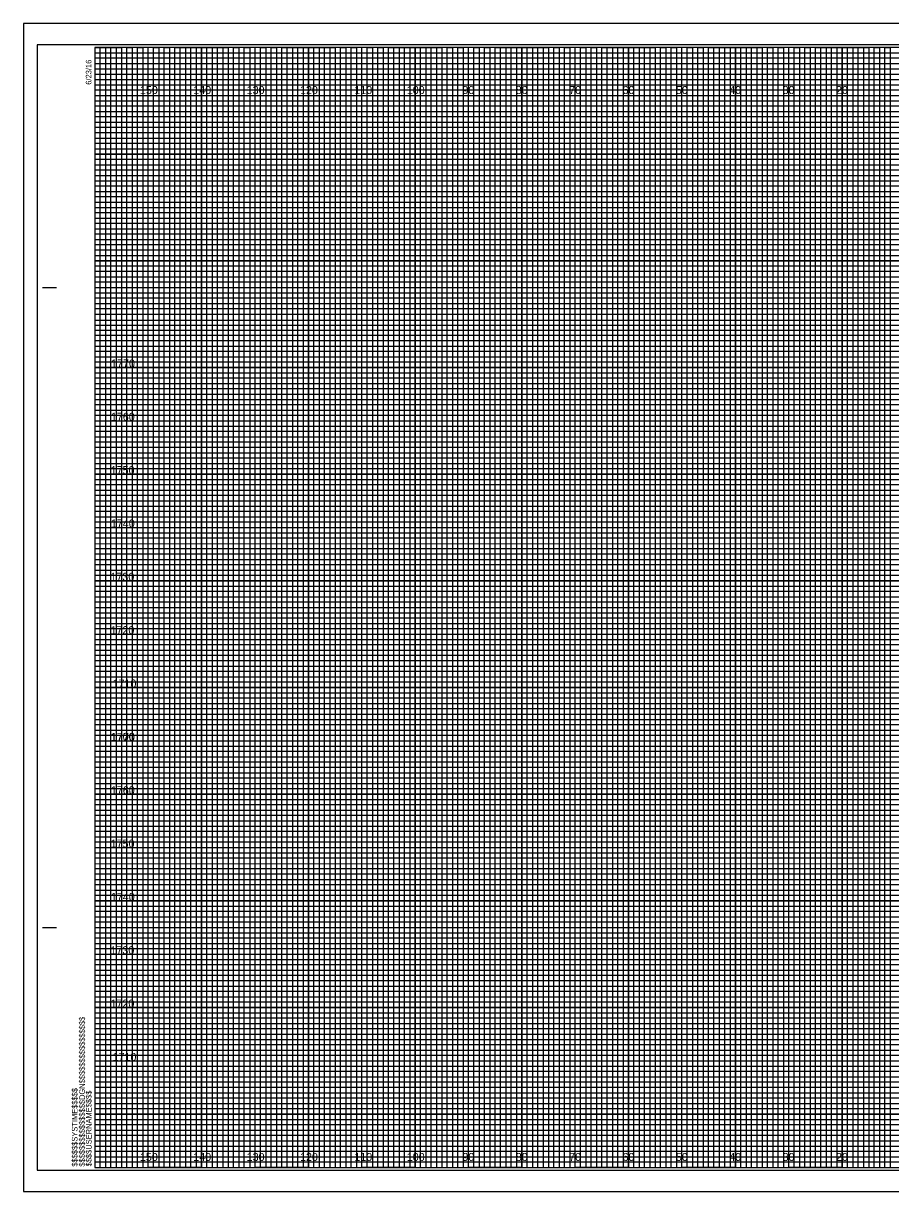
# Model space of a CAD drawing. Extents: x -15 to 323, y -5 to 6170.
# Drawn here: x -13.4 to 149.1, y 5275.5 to 5494.5 of the extents above; entities that cross this region are included whole.
import ezdxf

# ---------------------------------------------------------------- set-up
doc = ezdxf.new("R2010")
doc.units = 0
for name, color, linetype in [('Prop XS DDE', 7, 'Continuous'), ('Prop XS DDE Slope Text', 7, 'Continuous'), ('Prop XS DDE Text', 7, 'Continuous'), ('Prop XS Earthwork Shape', 7, 'Continuous'), ('Prop XS Noise Wall', 7, 'Continuous'), ('Prop XS Retaining Wall', 7, 'Continuous'), ('Prop XS Station Labels', 7, 'Continuous'), ('Scratch_Level_3', 7, 'Continuous'), ('Scratch_Level_7', 7, 'Continuous'), ('Scratch_Level_8', 7, 'Continuous'), ('Sheet Cross Section Grid Minor 1 CELL', 7, 'Continuous')]:
    doc.layers.add(name, color=color, linetype=linetype)

msp = doc.modelspace()

# ---------------------------------------------------------------- linework, layer by layer
at = {"layer": 'Prop XS DDE'}
msp.add_lwpolyline([(-13.4, 5275.5), (323.3, 5275.5), (323.3, 5494.5), (-13.4, 5494.5)], close=True, dxfattribs=at)
at = {"layer": 'Prop XS DDE Slope Text'}
msp.add_lwpolyline([(-10.8, 5279.5), (322.4, 5279.5), (322.4, 5490.5), (-10.8, 5490.5)], close=True, dxfattribs=at)
at = {"layer": 'Prop XS DDE Text'}
for p, q in [((10, 5280), (10, 5490)), ((20, 5280), (20, 5490)), ((30, 5280), (30, 5490)), ((40, 5280), (40, 5490)), ((50, 5280), (50, 5490)), ((60, 5280), (60, 5490)), ((70, 5280), (70, 5490)), ((80, 5280), (80, 5490)), ((90, 5280), (90, 5490)), ((100, 5280), (100, 5490)), ((110, 5280), (110, 5490)), ((120, 5280), (120, 5490)), ((130, 5280), (130, 5490)), ((140, 5280), (140, 5490)), ((0, 5480), (320, 5480)), ((0, 5470), (320, 5470)), ((0, 5460), (320, 5460)), ((0, 5450), (320, 5450)), ((0, 5440), (320, 5440)), ((0, 5430), (320, 5430)), ((0, 5420), (320, 5420)), ((0, 5410), (320, 5410)), ((0, 5400), (320, 5400)), ((0, 5390), (320, 5390)), ((0, 5380), (320, 5380)), ((0, 5370), (320, 5370)), ((0, 5360), (320, 5360)), ((0, 5350), (320, 5350)), ((0, 5340), (320, 5340)), ((0, 5330), (320, 5330)), ((0, 5320), (320, 5320)), ((0, 5310), (320, 5310)), ((0, 5300), (320, 5300)), ((0, 5290), (320, 5290))]:
    msp.add_line(p, q, dxfattribs=at)
at = {"layer": 'Prop XS Earthwork Shape'}
for p, q in [((10, 5490), (0, 5490)), ((10, 5280), (10, 5490)), ((30, 5490), (20, 5490)), ((20, 5490), (20, 5280)), ((30, 5280), (30, 5490)), ((50, 5490), (40, 5490)), ((40, 5490), (40, 5280)), ((50, 5280), (50, 5490)), ((70, 5490), (60, 5490)), ((60, 5490), (60, 5280)), ((70, 5280), (70, 5490)), ((90, 5490), (80, 5490)), ((80, 5490), (80, 5280)), ((90, 5280), (90, 5490)), ((110, 5490), (100, 5490)), ((100, 5490), (100, 5280)), ((110, 5280), (110, 5490)), ((130, 5490), (120, 5490)), ((120, 5490), (120, 5280)), ((130, 5280), (130, 5490)), ((150, 5490), (140, 5490)), ((140, 5490), (140, 5280)), ((20, 5280), (10, 5280)), ((40, 5280), (30, 5280)), ((60, 5280), (50, 5280)), ((80, 5280), (70, 5280)), ((100, 5280), (90, 5280)), ((120, 5280), (110, 5280)), ((140, 5280), (130, 5280))]:
    msp.add_line(p, q, dxfattribs=at)
for points in [[(0, 5480), (320, 5480), (320, 5470), (0, 5470)], [(0, 5460), (320, 5460), (320, 5450), (0, 5450)], [(0, 5440), (320, 5440), (320, 5430), (0, 5430)], [(0, 5420), (320, 5420), (320, 5410), (0, 5410)], [(0, 5400), (320, 5400), (320, 5390), (0, 5390)], [(0, 5380), (320, 5380), (320, 5370), (0, 5370)], [(0, 5360), (320, 5360), (320, 5350), (0, 5350)], [(0, 5340), (320, 5340), (320, 5330), (0, 5330)], [(0, 5320), (320, 5320), (320, 5310), (0, 5310)], [(0, 5300), (320, 5300), (320, 5290), (0, 5290)]]:
    msp.add_lwpolyline(points, dxfattribs=at)
at = {"layer": 'Prop XS Noise Wall'}
for p, q in [((-9.8, 5445), (-7.3, 5445)), ((-9.7, 5445), (-7.2, 5445)), ((-9.8, 5325), (-7.3, 5325)), ((-9.7, 5325), (-7.2, 5325)), ((0, 5280), (0, 5280)), ((0, 5280), (0, 5280)), ((0, 5280), (0, 5280)), ((0, 5280), (0, 5280)), ((0, 5280), (0, 5280)), ((0, 5280), (0, 5280)), ((0, 5280), (0, 5280))]:
    msp.add_line(p, q, dxfattribs=at)
msp.add_lwpolyline([(320, 5490), (0, 5490), (0, 5280), (320, 5280)], close=True, dxfattribs=at)
at = {"layer": 'Prop XS Retaining Wall'}
for points in [[(0, 5280), (1, 5280), (1, 5490), (2, 5490), (2, 5280)], [(2, 5280), (3, 5280), (3, 5490), (4, 5490), (4, 5280)], [(5, 5280), (6, 5280), (6, 5490), (7, 5490), (7, 5280)], [(7, 5280), (8, 5280), (8, 5490), (9, 5490), (9, 5280)], [(10, 5280), (11, 5280), (11, 5490), (12, 5490), (12, 5280)], [(12, 5280), (13, 5280), (13, 5490), (14, 5490), (14, 5280)], [(15, 5280), (16, 5280), (16, 5490), (17, 5490), (17, 5280)], [(17, 5280), (18, 5280), (18, 5490), (19, 5490), (19, 5280)], [(20, 5280), (21, 5280), (21, 5490), (22, 5490), (22, 5280)], [(22, 5280), (23, 5280), (23, 5490), (24, 5490), (24, 5280)], [(25, 5280), (26, 5280), (26, 5490), (27, 5490), (27, 5280)], [(27, 5280), (28, 5280), (28, 5490), (29, 5490), (29, 5280)], [(30, 5280), (31, 5280), (31, 5490), (32, 5490), (32, 5280)], [(32, 5280), (33, 5280), (33, 5490), (34, 5490), (34, 5280)], [(35, 5280), (36, 5280), (36, 5490), (37, 5490), (37, 5280)], [(37, 5280), (38, 5280), (38, 5490), (39, 5490), (39, 5280)], [(40, 5280), (41, 5280), (41, 5490), (42, 5490), (42, 5280)], [(42, 5280), (43, 5280), (43, 5490), (44, 5490), (44, 5280)], [(45, 5280), (46, 5280), (46, 5490), (47, 5490), (47, 5280)], [(47, 5280), (48, 5280), (48, 5490), (49, 5490), (49, 5280)], [(50, 5280), (51, 5280), (51, 5490), (52, 5490), (52, 5280)], [(52, 5280), (53, 5280), (53, 5490), (54, 5490), (54, 5280)], [(55, 5280), (56, 5280), (56, 5490), (57, 5490), (57, 5280)], [(57, 5280), (58, 5280), (58, 5490), (59, 5490), (59, 5280)], [(60, 5280), (61, 5280), (61, 5490), (62, 5490), (62, 5280)], [(62, 5280), (63, 5280), (63, 5490), (64, 5490), (64, 5280)], [(65, 5280), (66, 5280), (66, 5490), (67, 5490), (67, 5280)], [(67, 5280), (68, 5280), (68, 5490), (69, 5490), (69, 5280)], [(70, 5280), (71, 5280), (71, 5490), (72, 5490), (72, 5280)], [(72, 5280), (73, 5280), (73, 5490), (74, 5490), (74, 5280)], [(75, 5280), (76, 5280), (76, 5490), (77, 5490), (77, 5280)], [(77, 5280), (78, 5280), (78, 5490), (79, 5490), (79, 5280)], [(80, 5280), (81, 5280), (81, 5490), (82, 5490), (82, 5280)], [(82, 5280), (83, 5280), (83, 5490), (84, 5490), (84, 5280)], [(85, 5280), (86, 5280), (86, 5490), (87, 5490), (87, 5280)], [(87, 5280), (88, 5280), (88, 5490), (89, 5490), (89, 5280)], [(90, 5280), (91, 5280), (91, 5490), (92, 5490), (92, 5280)], [(92, 5280), (93, 5280), (93, 5490), (94, 5490), (94, 5280)], [(95, 5280), (96, 5280), (96, 5490), (97, 5490), (97, 5280)], [(97, 5280), (98, 5280), (98, 5490), (99, 5490), (99, 5280)], [(100, 5280), (101, 5280), (101, 5490), (102, 5490), (102, 5280)], [(102, 5280), (103, 5280), (103, 5490), (104, 5490), (104, 5280)], [(105, 5280), (106, 5280), (106, 5490), (107, 5490), (107, 5280)], [(107, 5280), (108, 5280), (108, 5490), (109, 5490), (109, 5280)], [(110, 5280), (111, 5280), (111, 5490), (112, 5490), (112, 5280)], [(112, 5280), (113, 5280), (113, 5490), (114, 5490), (114, 5280)], [(115, 5280), (116, 5280), (116, 5490), (117, 5490), (117, 5280)], [(117, 5280), (118, 5280), (118, 5490), (119, 5490), (119, 5280)], [(120, 5280), (121, 5280), (121, 5490), (122, 5490), (122, 5280)], [(122, 5280), (123, 5280), (123, 5490), (124, 5490), (124, 5280)], [(125, 5280), (126, 5280), (126, 5490), (127, 5490), (127, 5280)], [(127, 5280), (128, 5280), (128, 5490), (129, 5490), (129, 5280)], [(130, 5280), (131, 5280), (131, 5490), (132, 5490), (132, 5280)], [(132, 5280), (133, 5280), (133, 5490), (134, 5490), (134, 5280)], [(135, 5280), (136, 5280), (136, 5490), (137, 5490), (137, 5280)], [(137, 5280), (138, 5280), (138, 5490), (139, 5490), (139, 5280)], [(140, 5280), (141, 5280), (141, 5490), (142, 5490), (142, 5280)], [(142, 5280), (143, 5280), (143, 5490), (144, 5490), (144, 5280)], [(145, 5280), (146, 5280), (146, 5490), (147, 5490), (147, 5280)], [(147, 5280), (148, 5280), (148, 5490), (149, 5490), (149, 5280)]]:
    msp.add_lwpolyline(points, dxfattribs=at)
at = {"layer": 'Prop XS Station Labels'}
for points in [[(0, 5490), (5, 5490), (5, 5280), (15, 5280), (15, 5490), (25, 5490), (25, 5280), (35, 5280), (35, 5490), (45, 5490), (45, 5280), (55, 5280), (55, 5490), (65, 5490), (65, 5280), (75, 5280), (75, 5490), (85, 5490), (85, 5280), (95, 5280), (95, 5490), (105, 5490), (105, 5280), (115, 5280), (115, 5490), (125, 5490), (125, 5280), (135, 5280), (135, 5490), (145, 5490), (145, 5280), (155, 5280)], [(0, 5485), (275, 5485)], [(0, 5465), (320, 5465), (320, 5475), (0, 5475)], [(0, 5445), (320, 5445), (320, 5455), (0, 5455)], [(0, 5425), (320, 5425), (320, 5435), (0, 5435)], [(0, 5405), (320, 5405), (320, 5415), (0, 5415)], [(0, 5385), (320, 5385), (320, 5395), (0, 5395)], [(0, 5365), (320, 5365), (320, 5375), (0, 5375)], [(0, 5345), (320, 5345), (320, 5355), (0, 5355)], [(0, 5325), (320, 5325), (320, 5335), (0, 5335)], [(0, 5305), (320, 5305), (320, 5315), (0, 5315)], [(0, 5285), (320, 5285), (320, 5295), (0, 5295)]]:
    msp.add_lwpolyline(points, dxfattribs=at)
at = {"layer": 'Scratch_Level_7'}
for p, q in [((323.3, 5494.5), (-13.4, 5494.5)), ((-13.4, 5494.5), (-13.4, 5275.5)), ((-13.4, 5275.5), (323.3, 5275.5))]:
    msp.add_line(p, q, dxfattribs=at)
at = {"layer": 'Sheet Cross Section Grid Minor 1 CELL'}
for p, q in [((0, 5489), (260, 5489)), ((260, 5487.98), (0, 5487.98)), ((0, 5487.98), (0, 5487)), ((0, 5487), (260, 5487)), ((260, 5485.89), (0, 5485.89)), ((0, 5485.89), (0, 5484)), ((0, 5484), (320, 5484))]:
    msp.add_line(p, q, dxfattribs=at)
for points in [[(0, 5483), (270, 5483), (320, 5483), (320, 5482), (0, 5482)], [(0, 5481), (320, 5481), (320, 5479), (0, 5479)], [(0, 5478), (320, 5478), (320, 5477), (0, 5476.98)], [(0, 5476), (320, 5476), (320, 5474), (0, 5474)], [(0, 5473), (320, 5473), (320, 5472), (0, 5472)], [(0, 5471), (320, 5471), (320, 5469), (0, 5469)], [(0, 5468), (320, 5468), (320, 5467), (0, 5467)], [(0, 5466), (320, 5466), (320, 5464), (0, 5464)], [(0, 5463), (320, 5463), (320, 5462), (0, 5462)], [(0, 5461), (320, 5461), (320, 5459), (0, 5459)], [(0, 5458), (320, 5458), (320, 5457), (0, 5457)], [(0, 5456), (320, 5456), (320, 5453.95), (320, 5453), (320, 5452), (0, 5452)], [(0, 5454), (320, 5454), (320, 5453), (0, 5453)], [(0, 5451), (320, 5451), (320, 5449), (0, 5449.03)], [(0, 5449.03), (320, 5449), (320, 5448), (0, 5448)], [(0, 5447), (320, 5447), (320, 5446), (0, 5446)], [(0, 5444), (320, 5444), (320, 5443), (0, 5443)], [(0, 5442), (320, 5442), (320, 5441), (0, 5441)], [(-0.07, 5438.89), (320, 5438.89), (320, 5437.88), (-0.07, 5437.88)], [(0, 5437), (320, 5437), (320, 5436), (0, 5436)], [(0, 5434), (320, 5434), (320, 5433), (0, 5433)], [(0, 5432), (320, 5432), (320, 5431), (0, 5431)], [(0, 5429), (320, 5429), (320, 5428), (0, 5428)], [(0, 5427), (320, 5427), (320, 5426), (0, 5426)], [(0, 5424), (320, 5424), (320, 5423), (0, 5423)], [(0, 5422), (320, 5422), (320, 5421), (0, 5421)], [(0, 5419), (320, 5419), (319.99, 5417.98), (0, 5418)], [(0, 5417), (320, 5417), (320, 5416), (0, 5416)], [(0, 5414), (320, 5414), (320, 5413), (0, 5413)], [(0, 5412), (320, 5412), (320, 5411), (0, 5411)], [(0, 5409), (320, 5409), (320, 5408), (0, 5408)], [(0, 5407), (320, 5407), (320, 5406), (0, 5406)], [(0, 5404), (320, 5404), (320, 5403), (0, 5403)], [(0, 5402), (320, 5402), (320, 5401), (0, 5401)], [(0, 5399), (320, 5399), (320, 5398), (0, 5398)], [(0, 5396.99), (320.07, 5396.91), (320, 5396), (0, 5396)], [(0, 5394), (320, 5394), (320, 5393), (0, 5393)], [(0, 5392), (320, 5392), (320, 5391), (0, 5391)], [(0, 5389), (320, 5389), (320, 5388), (0, 5388)], [(0, 5387), (320, 5387), (320, 5386), (0, 5386)], [(0, 5384), (320, 5384), (320, 5383), (0, 5383)], [(0, 5382), (320, 5382), (320, 5381), (0, 5381)], [(0, 5379), (320, 5379), (320, 5378), (0, 5378)], [(0, 5377), (320, 5377), (320, 5376), (0, 5376)], [(0, 5374), (320, 5374), (320, 5373), (0, 5373)], [(0, 5372), (320, 5372), (320, 5371), (0, 5371)], [(0, 5369), (320, 5369), (320, 5368), (0, 5368)], [(0, 5367), (320, 5367), (320, 5366), (0, 5366)], [(0, 5364), (320, 5364), (320, 5363), (0, 5363)], [(0, 5362), (320, 5362), (320, 5361), (0, 5361)], [(0, 5359), (320, 5359), (319.99, 5357.98), (0, 5358)], [(0, 5357), (320, 5357), (320, 5356), (0, 5356)], [(0, 5354), (320, 5354), (320, 5353), (0, 5353)], [(0, 5352), (320, 5352), (320, 5351), (0, 5351)], [(0, 5349), (320, 5349), (320, 5348), (0, 5348)], [(0, 5347), (320, 5347), (320, 5346), (0, 5346)], [(0, 5344), (320, 5344), (320, 5343), (0, 5343)], [(0, 5342), (320, 5342), (320, 5341), (0, 5341)], [(0, 5339), (320, 5339), (320, 5338), (0, 5338)], [(0, 5336.99), (320.07, 5336.91), (320, 5336), (0, 5336)], [(0, 5334), (320, 5334), (320, 5333), (0, 5333)], [(0, 5332), (320, 5332), (320, 5331), (0, 5331)], [(0, 5329), (320, 5329), (320, 5328), (0, 5328)], [(0, 5327), (320, 5327), (320, 5326), (0, 5326)], [(0, 5324), (320, 5324), (320, 5323), (0, 5323)], [(0, 5322), (320, 5322), (320, 5321), (0, 5321)], [(0, 5319), (320, 5319), (320, 5318), (0, 5318)], [(0, 5317), (320, 5317), (320, 5316), (0, 5316)], [(0, 5314), (320, 5314), (320, 5313), (0, 5313)], [(0, 5312), (320, 5312), (320, 5311), (0, 5311)], [(0, 5309), (320, 5309), (320, 5308), (0, 5308)], [(0, 5307), (320, 5307), (320, 5306), (0, 5306)], [(0, 5304), (320, 5304), (320, 5303), (0, 5303)], [(0, 5302), (320, 5302), (320, 5301), (0, 5301)], [(0, 5299), (320, 5299), (320, 5298), (0, 5298)], [(0, 5297), (320, 5297), (320, 5296), (0, 5296)], [(0, 5294), (320, 5294), (320, 5293), (0, 5293)], [(0, 5292), (320, 5292), (320, 5291), (0, 5291)], [(0, 5289), (320, 5289), (320, 5288), (0, 5288)], [(0, 5287), (320, 5287), (320, 5286), (0, 5286)], [(0, 5284), (320, 5284), (320, 5283), (0, 5283)], [(0, 5282), (320, 5282), (320, 5281), (0, 5281)]]:
    msp.add_lwpolyline(points, dxfattribs=at)

# ---------------------------------------------------------------- texts
at = {"layer": 'Prop XS Noise Wall'}
for s, p in [('6/23/16', (-0.65, 5483)), ('$$$$$$$$$$$$$$$$DGN$$$$$$$$$$$$$$$$', (-1.88, 5280.18)), ('$$$$$$SYSTIME$$$$$', (-3.26, 5280.18)), ('$$$$USERNAME$$$$', (-0.62, 5280.23))]:
    msp.add_text(s, height=1.05, rotation=90, dxfattribs=at).set_placement(p)
at = {"layer": 'Scratch_Level_3'}
for s, p in [('1770', (3.04, 5430)), ('1760', (3, 5420)), ('1750', (2.96, 5410)), ('1740', (3, 5400)), ('1730', (2.92, 5390)), ('1720', (2.93, 5380)), ('1710', (3.31, 5370)), ('1700', (2.98, 5360)), ('1770', (3.04, 5360)), ('1760', (3, 5350)), ('1750', (2.96, 5340)), ('1740', (3, 5330)), ('1730', (2.92, 5320)), ('1720', (2.93, 5310)), ('1710', (3.31, 5300))]:
    msp.add_text(s, height=1.5, dxfattribs=at).set_placement(p)
at = {"layer": 'Scratch_Level_8'}
for s, p in [('150', (8.44, 5481.25)), ('140', (18.44, 5481.25)), ('130', (28.44, 5481.25)), ('120', (38.44, 5481.25)), ('110', (48.62, 5481.25)), ('100', (58.44, 5481.25)), ('90', (68.86, 5481.25)), ('80', (78.86, 5481.25)), ('70', (88.86, 5481.25)), ('60', (98.86, 5481.25)), ('50', (108.86, 5481.25)), ('40', (118.86, 5481.25)), ('30', (128.86, 5481.25)), ('20', (138.86, 5481.25)), ('150', (8.44, 5281.25)), ('140', (18.44, 5281.25)), ('130', (28.44, 5281.25)), ('120', (38.44, 5281.25)), ('110', (48.62, 5281.25)), ('100', (58.44, 5281.25)), ('90', (68.86, 5281.25)), ('80', (78.86, 5281.25)), ('70', (88.86, 5281.25)), ('60', (98.86, 5281.25)), ('50', (108.86, 5281.25)), ('40', (118.86, 5281.25)), ('30', (128.86, 5281.25)), ('20', (138.86, 5281.25))]:
    msp.add_text(s, height=1.5, dxfattribs=at).set_placement(p)

doc.saveas('drawing.dxf')
